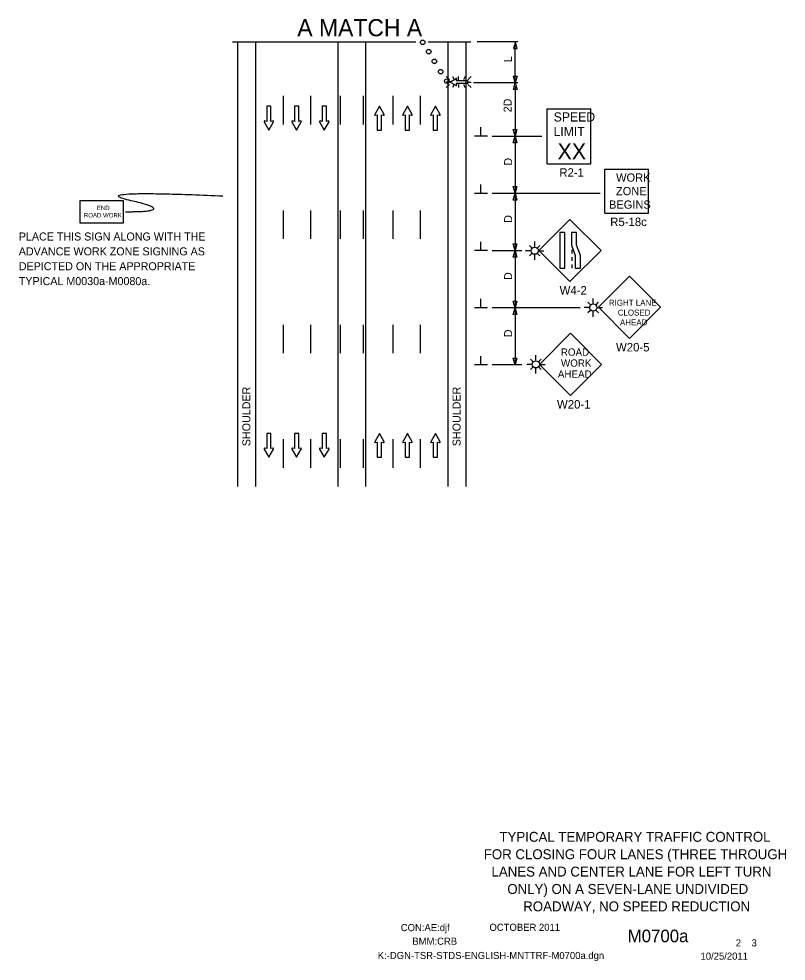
# Model space of a CAD drawing. Extents: x 16038 to 19504, y 5920 to 8321.
# Drawn here: x 17786 to 18457, y 7218 to 8042 of the extents above; entities that cross this region are included whole.
import ezdxf

# ---------------------------------------------------------------- set-up
doc = ezdxf.new("R2010")
doc.units = 0
for name, color, linetype in [('BORDER', 7, 'Continuous'), ('BORDER_SIGNAL_WO', 7, 'Continuous'), ('MT_SCRATCH_LEVEL_E', 7, 'Continuous'), ('PAVT_EDGE_EX', 7, 'Continuous'), ('TRAFFIC_SIGNS_PR', 7, 'Continuous'), ('TYPICAL_TEXT_DIMEN_PR', 7, 'Continuous')]:
    doc.layers.add(name, color=color, linetype=linetype)

msp = doc.modelspace()

# ---------------------------------------------------------------- linework, layer by layer
at = {"layer": 'BORDER'}
for p, q in [((18318.25, 7297.5), (18318.25, 7297.5)), ((18318.25, 7291.25), (18318.25, 7291.25))]:
    msp.add_line(p, q, dxfattribs=at)
at = {"layer": 'MT_SCRATCH_LEVEL_E'}
for p, q in [((18006.14, 7965.55), (18002.4, 7965.55)), ((18002.4, 7965.55), (18002.4, 7952.29)), ((18006.14, 7965.55), (18002.4, 7965.55)), ((18002.4, 7965.55), (18002.4, 7952.29)), ((18006.14, 7952.29), (18006.14, 7965.55)), ((18006.14, 7952.29), (18006.14, 7965.55)), ((18030.4, 7965.55), (18026.65, 7965.55)), ((18026.65, 7965.55), (18026.65, 7952.29)), ((18030.4, 7965.55), (18026.65, 7965.55)), ((18026.65, 7965.55), (18026.65, 7952.29)), ((18030.4, 7952.29), (18030.4, 7965.55)), ((18030.4, 7952.29), (18030.4, 7965.55)), ((18054.65, 7965.55), (18050.91, 7965.55)), ((18050.91, 7965.55), (18050.91, 7952.29)), ((18054.65, 7965.55), (18050.91, 7965.55)), ((18050.91, 7965.55), (18050.91, 7952.29)), ((18054.65, 7952.29), (18054.65, 7965.55)), ((18054.65, 7952.29), (18054.65, 7965.55)), ((18100.97, 7965.55), (18096.86, 7958.31)), ((18100.97, 7965.55), (18096.86, 7958.31)), ((18105.12, 7958.31), (18100.97, 7965.55)), ((18105.12, 7958.31), (18100.97, 7965.55)), ((18125.47, 7965.55), (18121.36, 7958.31)), ((18125.47, 7965.55), (18121.36, 7958.31)), ((18129.61, 7958.31), (18125.47, 7965.55)), ((18129.61, 7958.31), (18125.47, 7965.55)), ((18149.96, 7965.55), (18145.85, 7958.31)), ((18149.96, 7965.55), (18145.85, 7958.31)), ((18154.11, 7958.31), (18149.96, 7965.55)), ((18154.11, 7958.31), (18149.96, 7965.55)), ((18000.14, 7951.92), (18004.29, 7944.68)), ((18000.14, 7951.92), (18004.29, 7944.68)), ((18002.4, 7952.29), (18000.62, 7952.6)), ((18002.4, 7952.29), (18000.62, 7952.6)), ((18004.29, 7944.68), (18008.4, 7951.92)), ((18004.29, 7944.68), (18008.4, 7951.92)), ((18007.92, 7952.6), (18006.14, 7952.29)), ((18007.92, 7952.6), (18006.14, 7952.29)), ((18024.4, 7951.92), (18028.55, 7944.68)), ((18024.4, 7951.92), (18028.55, 7944.68)), ((18026.65, 7952.29), (18024.88, 7952.6)), ((18026.65, 7952.29), (18024.88, 7952.6)), ((18028.55, 7944.68), (18032.66, 7951.92)), ((18028.55, 7944.68), (18032.66, 7951.92)), ((18032.17, 7952.6), (18030.4, 7952.29)), ((18032.17, 7952.6), (18030.4, 7952.29)), ((18048.65, 7951.92), (18052.8, 7944.68)), ((18048.65, 7951.92), (18052.8, 7944.68)), ((18050.91, 7952.29), (18049.13, 7952.6)), ((18050.91, 7952.29), (18049.13, 7952.6)), ((18052.8, 7944.68), (18056.91, 7951.92)), ((18052.8, 7944.68), (18056.91, 7951.92)), ((18056.43, 7952.6), (18054.65, 7952.29)), ((18056.43, 7952.6), (18054.65, 7952.29)), ((18097.34, 7957.62), (18099.12, 7957.94)), ((18097.34, 7957.62), (18099.12, 7957.94)), ((18099.12, 7957.94), (18099.12, 7944.68)), ((18099.12, 7957.94), (18099.12, 7944.68)), ((18102.86, 7944.68), (18102.86, 7957.94)), ((18102.86, 7957.94), (18104.64, 7957.62)), ((18102.86, 7944.68), (18102.86, 7957.94)), ((18102.86, 7957.94), (18104.64, 7957.62)), ((18121.84, 7957.62), (18123.62, 7957.94)), ((18121.84, 7957.62), (18123.62, 7957.94)), ((18123.62, 7957.94), (18123.62, 7944.68)), ((18123.62, 7957.94), (18123.62, 7944.68)), ((18127.36, 7944.68), (18127.36, 7957.94)), ((18127.36, 7957.94), (18129.14, 7957.62)), ((18127.36, 7944.68), (18127.36, 7957.94)), ((18127.36, 7957.94), (18129.14, 7957.62)), ((18146.33, 7957.62), (18148.11, 7957.94)), ((18146.33, 7957.62), (18148.11, 7957.94)), ((18148.11, 7957.94), (18148.11, 7944.68)), ((18148.11, 7957.94), (18148.11, 7944.68)), ((18151.85, 7944.68), (18151.85, 7957.94)), ((18151.85, 7957.94), (18153.63, 7957.62)), ((18151.85, 7944.68), (18151.85, 7957.94)), ((18151.85, 7957.94), (18153.63, 7957.62)), ((18099.12, 7944.68), (18102.86, 7944.68)), ((18099.12, 7944.68), (18102.86, 7944.68)), ((18123.62, 7944.68), (18127.36, 7944.68)), ((18123.62, 7944.68), (18127.36, 7944.68)), ((18148.11, 7944.68), (18151.85, 7944.68)), ((18148.11, 7944.68), (18151.85, 7944.68)), ((18006.14, 7679.44), (18002.4, 7679.44)), ((18002.4, 7679.44), (18002.4, 7666.18)), ((18006.14, 7679.44), (18002.4, 7679.44)), ((18002.4, 7679.44), (18002.4, 7666.18)), ((18006.14, 7666.18), (18006.14, 7679.44)), ((18006.14, 7666.18), (18006.14, 7679.44)), ((18030.4, 7679.44), (18026.65, 7679.44)), ((18026.65, 7679.44), (18026.65, 7666.18)), ((18030.4, 7679.44), (18026.65, 7679.44)), ((18026.65, 7679.44), (18026.65, 7666.18)), ((18030.4, 7666.18), (18030.4, 7679.44)), ((18030.4, 7666.18), (18030.4, 7679.44)), ((18054.65, 7679.44), (18050.91, 7679.44)), ((18050.91, 7679.44), (18050.91, 7666.18)), ((18054.65, 7679.44), (18050.91, 7679.44)), ((18050.91, 7679.44), (18050.91, 7666.18)), ((18054.65, 7666.18), (18054.65, 7679.44)), ((18054.65, 7666.18), (18054.65, 7679.44)), ((18100.97, 7679.44), (18096.86, 7672.2)), ((18100.97, 7679.44), (18096.86, 7672.2)), ((18105.12, 7672.2), (18100.97, 7679.44)), ((18105.12, 7672.2), (18100.97, 7679.44)), ((18125.47, 7679.44), (18121.36, 7672.2)), ((18125.47, 7679.44), (18121.36, 7672.2)), ((18129.61, 7672.2), (18125.47, 7679.44)), ((18129.61, 7672.2), (18125.47, 7679.44)), ((18149.96, 7679.44), (18145.85, 7672.2)), ((18149.96, 7679.44), (18145.85, 7672.2)), ((18154.11, 7672.2), (18149.96, 7679.44)), ((18154.11, 7672.2), (18149.96, 7679.44)), ((18097.34, 7671.52), (18099.12, 7671.83)), ((18097.34, 7671.52), (18099.12, 7671.83)), ((18099.12, 7671.83), (18099.12, 7658.57)), ((18099.12, 7671.83), (18099.12, 7658.57)), ((18102.86, 7658.57), (18102.86, 7671.83)), ((18102.86, 7671.83), (18104.64, 7671.52)), ((18102.86, 7658.57), (18102.86, 7671.83)), ((18102.86, 7671.83), (18104.64, 7671.52)), ((18121.84, 7671.52), (18123.62, 7671.83)), ((18121.84, 7671.52), (18123.62, 7671.83)), ((18123.62, 7671.83), (18123.62, 7658.57)), ((18123.62, 7671.83), (18123.62, 7658.57)), ((18127.36, 7658.57), (18127.36, 7671.83)), ((18127.36, 7671.83), (18129.14, 7671.52)), ((18127.36, 7658.57), (18127.36, 7671.83)), ((18127.36, 7671.83), (18129.14, 7671.52)), ((18146.33, 7671.52), (18148.11, 7671.83)), ((18146.33, 7671.52), (18148.11, 7671.83)), ((18148.11, 7671.83), (18148.11, 7658.57)), ((18148.11, 7671.83), (18148.11, 7658.57)), ((18151.85, 7658.57), (18151.85, 7671.83)), ((18151.85, 7671.83), (18153.63, 7671.52)), ((18151.85, 7658.57), (18151.85, 7671.83)), ((18151.85, 7671.83), (18153.63, 7671.52)), ((18000.14, 7665.81), (18004.29, 7658.57)), ((18000.14, 7665.81), (18004.29, 7658.57)), ((18002.4, 7666.18), (18000.62, 7666.5)), ((18002.4, 7666.18), (18000.62, 7666.5)), ((18004.29, 7658.57), (18008.4, 7665.81)), ((18004.29, 7658.57), (18008.4, 7665.81)), ((18007.92, 7666.5), (18006.14, 7666.18)), ((18007.92, 7666.5), (18006.14, 7666.18)), ((18024.4, 7665.81), (18028.55, 7658.57)), ((18024.4, 7665.81), (18028.55, 7658.57)), ((18026.65, 7666.18), (18024.88, 7666.5)), ((18026.65, 7666.18), (18024.88, 7666.5)), ((18028.55, 7658.57), (18032.66, 7665.81)), ((18028.55, 7658.57), (18032.66, 7665.81)), ((18032.17, 7666.5), (18030.4, 7666.18)), ((18032.17, 7666.5), (18030.4, 7666.18)), ((18048.65, 7665.81), (18052.8, 7658.57)), ((18048.65, 7665.81), (18052.8, 7658.57)), ((18050.91, 7666.18), (18049.13, 7666.5)), ((18050.91, 7666.18), (18049.13, 7666.5)), ((18052.8, 7658.57), (18056.91, 7665.81)), ((18052.8, 7658.57), (18056.91, 7665.81)), ((18056.43, 7666.5), (18054.65, 7666.18)), ((18056.43, 7666.5), (18054.65, 7666.18)), ((18099.12, 7658.57), (18102.86, 7658.57)), ((18099.12, 7658.57), (18102.86, 7658.57)), ((18123.62, 7658.57), (18127.36, 7658.57)), ((18123.62, 7658.57), (18127.36, 7658.57)), ((18148.11, 7658.57), (18151.85, 7658.57)), ((18148.11, 7658.57), (18151.85, 7658.57))]:
    msp.add_line(p, q, dxfattribs=at)
for centre, start, end in [((18097.27, 7958.08), 150.42484, 279.96381), ((18097.27, 7958.08), 150.42484, 279.96381), ((18104.71, 7958.08), 260.03619, 29.77312), ((18104.71, 7958.08), 260.03619, 29.77312), ((18121.76, 7958.08), 150.42484, 279.96381), ((18121.76, 7958.08), 150.42484, 279.96381), ((18129.2, 7958.08), 260.03619, 29.77312), ((18129.2, 7958.08), 260.03619, 29.77312), ((18146.26, 7958.08), 150.42484, 279.96381), ((18146.26, 7958.08), 150.42484, 279.96381), ((18153.7, 7958.08), 260.03619, 29.77312), ((18153.7, 7958.08), 260.03619, 29.77312), ((18000.55, 7952.14), 80.03619, 209.77312), ((18000.55, 7952.14), 80.03619, 209.77312), ((18007.99, 7952.14), 330.42484, 99.96381), ((18007.99, 7952.14), 330.42484, 99.96381), ((18024.81, 7952.14), 80.03619, 209.77312), ((18024.81, 7952.14), 80.03619, 209.77312), ((18032.25, 7952.14), 330.42484, 99.96381), ((18032.25, 7952.14), 330.42484, 99.96381), ((18049.06, 7952.14), 80.03619, 209.77312), ((18049.06, 7952.14), 80.03619, 209.77312), ((18056.5, 7952.14), 330.42484, 99.96381), ((18056.5, 7952.14), 330.42484, 99.96381), ((18097.27, 7671.97), 150.42484, 279.96381), ((18097.27, 7671.97), 150.42484, 279.96381), ((18104.71, 7671.98), 260.03619, 29.77312), ((18104.71, 7671.98), 260.03619, 29.77312), ((18121.76, 7671.97), 150.42484, 279.96381), ((18121.76, 7671.97), 150.42484, 279.96381), ((18129.2, 7671.98), 260.03619, 29.77312), ((18129.2, 7671.98), 260.03619, 29.77312), ((18146.26, 7671.97), 150.42484, 279.96381), ((18146.26, 7671.97), 150.42484, 279.96381), ((18153.7, 7671.98), 260.03619, 29.77312), ((18153.7, 7671.98), 260.03619, 29.77312), ((18000.55, 7666.04), 80.03619, 209.77312), ((18000.55, 7666.04), 80.03619, 209.77312), ((18007.99, 7666.04), 330.42484, 99.96381), ((18007.99, 7666.04), 330.42484, 99.96381), ((18024.81, 7666.04), 80.03619, 209.77312), ((18024.81, 7666.04), 80.03619, 209.77312), ((18032.25, 7666.04), 330.42484, 99.96381), ((18032.25, 7666.04), 330.42484, 99.96381), ((18049.06, 7666.04), 80.03619, 209.77312), ((18049.06, 7666.04), 80.03619, 209.77312), ((18056.5, 7666.04), 330.42484, 99.96381), ((18056.5, 7666.04), 330.42484, 99.96381)]:
    msp.add_arc(centre, 0.463, start, end, dxfattribs=at)
at = {"layer": 'PAVT_EDGE_EX'}
for p, q in [((17976.73, 8021.87), (17976.73, 7633.14)), ((17992.73, 8021.87), (17992.73, 7633.14)), ((18064.73, 8021.87), (18064.73, 7633.14)), ((18088.73, 8021.87), (18088.73, 7633.14)), ((18160.73, 8021.87), (18160.73, 7633.14)), ((18176.73, 8021.87), (18176.73, 7633.14))]:
    msp.add_line(p, q, dxfattribs=at)
at = {"layer": 'TRAFFIC_SIGNS_PR'}
for p, q in [((18159.43, 7991.52), (18162.25, 7988.7)), ((18164.86, 7991.52), (18166.07, 7989.43)), ((18170.33, 7988.7), (18170.33, 7991.52)), ((18176.12, 7991.52), (18174.49, 7988.7)), ((18178.42, 7988.7), (18181.24, 7991.52)), ((18162.25, 7986.67), (18159.43, 7986.67)), ((18159.43, 7981.82), (18162.25, 7984.64)), ((18166.15, 7984), (18164.89, 7981.82)), ((18170.33, 7984.64), (18170.33, 7981.82)), ((18174.47, 7984.64), (18176.1, 7981.82)), ((18178.42, 7986.67), (18181.24, 7986.67)), ((18178.42, 7984.64), (18181.24, 7981.82)), ((18247.7, 7963.28), (18286.1, 7963.28)), ((18247.7, 7915.28), (18247.7, 7963.28)), ((18286.1, 7915.28), (18286.1, 7963.28)), ((18247.7, 7915.28), (18286.1, 7915.28)), ((18298.11, 7872.16), (18298.11, 7910.56)), ((18298.11, 7910.56), (18336.51, 7910.56)), ((18336.51, 7872.16), (18336.51, 7910.56)), ((18298.11, 7872.16), (18336.51, 7872.16)), ((18267.74, 7866.59), (18240.58, 7839.43)), ((18294.89, 7839.43), (18267.74, 7866.59)), ((18234.34, 7841.73), (18232.24, 7843.84)), ((18236.85, 7842.77), (18236.85, 7847.27)), ((18239.36, 7841.73), (18241.47, 7843.84)), ((18233.7, 7839.22), (18228.87, 7839.22)), ((18234.34, 7836.71), (18232.24, 7834.61)), ((18236.85, 7831.27), (18236.85, 7835.67)), ((18239.36, 7836.71), (18241.46, 7834.61)), ((18240, 7839.22), (18244.88, 7839.22)), ((18240.58, 7839.43), (18267.74, 7812.28)), ((18267.74, 7812.28), (18294.89, 7839.43)), ((18269.38, 7839.92), (18269.38, 7836.72)), ((18269.38, 7833.52), (18269.38, 7830.32)), ((18269.38, 7827.12), (18269.38, 7823.92)), ((18319.82, 7816.87), (18292.66, 7789.71)), ((18346.97, 7789.71), (18319.82, 7816.87)), ((18285.59, 7792.01), (18283.48, 7794.11)), ((18288.1, 7793.05), (18288.1, 7797.55)), ((18290.61, 7792.01), (18292.72, 7794.11)), ((18284.94, 7789.49), (18280.11, 7789.49)), ((18285.58, 7786.98), (18283.48, 7784.87)), ((18288.1, 7781.53), (18288.1, 7785.94)), ((18290.61, 7786.98), (18292.72, 7784.87)), ((18291.25, 7789.49), (18296.13, 7789.49)), ((18292.66, 7789.71), (18319.82, 7762.56)), ((18319.82, 7762.56), (18346.97, 7789.71)), ((18268.2, 7767.01), (18241.02, 7739.82)), ((18295.39, 7739.82), (18268.2, 7767.01)), ((18235.35, 7742.34), (18233.24, 7744.45)), ((18237.86, 7743.38), (18237.86, 7747.88)), ((18240.38, 7742.34), (18242.49, 7744.45)), ((18234.71, 7739.82), (18229.87, 7739.82)), ((18235.35, 7737.31), (18233.24, 7735.2)), ((18237.86, 7731.86), (18237.86, 7736.27)), ((18240.38, 7737.31), (18242.48, 7735.2)), ((18241.02, 7739.82), (18245.9, 7739.82)), ((18241.02, 7739.82), (18268.2, 7712.64)), ((18268.2, 7712.64), (18295.39, 7739.82))]:
    msp.add_line(p, q, dxfattribs=at)
for points in [[(18168.01, 7983.65), (18162.7, 7986.67), (18168.01, 7989.71)], [(18168.51, 7989.35), (18168.28, 7988.05), (18178, 7988.05), (18178, 7985.31), (18168.28, 7985.31), (18168.51, 7984.01)]]:
    msp.add_lwpolyline(points, dxfattribs=at)
for points in [[(17838.87, 7863.56), (17877.26, 7863.56), (17877.26, 7882.76), (17838.87, 7882.76)], [(18258.84, 7855.17), (18258.84, 7823.92), (18263.33, 7823.92), (18263.33, 7855.17)], [(18268.98, 7855.17), (18268.98, 7843.99), (18272.32, 7835.11), (18272.32, 7823.92), (18276.82, 7823.92), (18276.82, 7835.11), (18273.47, 7843.99), (18273.47, 7855.17)]]:
    msp.add_lwpolyline(points, close=True, dxfattribs=at)
for centre, radius in [((18138.91, 8021.37), 2), ((18144.15, 8013.2), 2), ((18149.13, 8004.78), 2), ((18154.63, 7995.74), 2), ((18159.96, 7987.38), 2), ((18236.85, 7839.22), 3.15), ((18288.1, 7789.49), 3.15), ((18237.86, 7739.83), 3.15)]:
    msp.add_circle(centre, radius, dxfattribs=at)
for centre, start, end in [((18168.17, 7989.41), 350.04067, 118.51671), ((18168.17, 7983.95), 241.10835, 9.26922)]:
    msp.add_arc(centre, 0.341, start, end, dxfattribs=at)
msp.add_open_spline([(17878.81, 7873.28), (17926.05, 7873.28), (17841.02, 7892.62), (17964.12, 7887.13)], degree=2, dxfattribs=at)
at = {"layer": 'TYPICAL_TEXT_DIMEN_PR'}
for p, q in [((17972.43, 8021.87), (18132.84, 8021.87)), ((18064.73, 8021.87), (18088.73, 8021.87)), ((18143.74, 8021.87), (18181.03, 8021.87)), ((18222.05, 8021.88), (18186.49, 8021.87)), ((18219.96, 8021.9), (18218.39, 8016.04)), ((18218.39, 8016.04), (18219.96, 8016.04)), ((18219.9, 7985.9), (18219.9, 8020.72)), ((18221.53, 8016.04), (18219.96, 8021.9)), ((18219.96, 8016.04), (18221.53, 8016.04)), ((18219.9, 7986.05), (18218.33, 7991.91)), ((18218.33, 7991.91), (18219.9, 7991.91)), ((18219.9, 7991.91), (18221.47, 7991.91)), ((18221.47, 7991.91), (18219.9, 7986.05)), ((18222.06, 7986.03), (18183.22, 7986.03)), ((18218.32, 7980.21), (18219.89, 7986.07)), ((18219.81, 7982.84), (18219.81, 7940.02)), ((18219.89, 7986.07), (18221.46, 7980.21)), ((18219.89, 7980.21), (18218.32, 7980.21)), ((18221.46, 7980.21), (18219.89, 7980.21)), ((18189.85, 7939.31), (18189.85, 7947.09)), ((18219.67, 7939.36), (18218.1, 7945.22)), ((18218.1, 7945.22), (18219.67, 7945.22)), ((18219.67, 7945.22), (18221.24, 7945.22)), ((18221.24, 7945.22), (18219.67, 7939.36)), ((18195.48, 7939.31), (18184.23, 7939.31)), ((18199.73, 7939.31), (18243.13, 7939.31)), ((18199.73, 7939.31), (18225.73, 7939.31)), ((18218.1, 7933.5), (18219.67, 7939.36)), ((18219.67, 7933.5), (18218.1, 7933.5)), ((18219.67, 7939.36), (18221.24, 7933.5)), ((18219.67, 7939.36), (18219.67, 7889.36)), ((18221.24, 7933.5), (18219.67, 7933.5)), ((18189.85, 7889.31), (18189.85, 7897.09)), ((18219.67, 7889.36), (18218.1, 7895.22)), ((18218.1, 7895.22), (18219.67, 7895.22)), ((18219.67, 7895.22), (18221.24, 7895.22)), ((18221.24, 7895.22), (18219.67, 7889.36)), ((18195.48, 7889.31), (18184.23, 7889.31)), ((18294.1, 7889.31), (18199.73, 7889.31)), ((18218.1, 7883.5), (18219.67, 7889.36)), ((18219.67, 7889.36), (18221.24, 7883.5)), ((18219.67, 7889.36), (18219.67, 7839.36)), ((18219.67, 7883.5), (18218.1, 7883.5)), ((18221.24, 7883.5), (18219.67, 7883.5)), ((18189.85, 7839.31), (18189.85, 7847.09)), ((18219.67, 7839.36), (18218.1, 7845.22)), ((18218.1, 7845.22), (18219.67, 7845.22)), ((18219.67, 7845.22), (18221.24, 7845.22)), ((18221.24, 7845.22), (18219.67, 7839.36)), ((18195.48, 7839.31), (18184.23, 7839.31)), ((18199.73, 7839.31), (18225.73, 7839.31)), ((18199.73, 7839.31), (18225.73, 7839.31)), ((18218.1, 7833.5), (18219.67, 7839.36)), ((18219.67, 7839.36), (18221.24, 7833.5)), ((18219.67, 7839.36), (18219.67, 7789.36)), ((18219.67, 7833.5), (18218.1, 7833.5)), ((18221.24, 7833.5), (18219.67, 7833.5)), ((18189.85, 7789.31), (18189.85, 7797.09)), ((18219.67, 7789.36), (18218.1, 7795.22)), ((18218.1, 7795.22), (18219.67, 7795.22)), ((18219.67, 7795.22), (18221.24, 7795.22)), ((18221.24, 7795.22), (18219.67, 7789.36)), ((18195.48, 7789.31), (18184.23, 7789.31)), ((18276.53, 7789.31), (18199.73, 7789.31)), ((18218.1, 7783.5), (18219.67, 7789.36)), ((18219.67, 7789.36), (18221.24, 7783.5)), ((18219.67, 7789.36), (18219.67, 7739.36)), ((18219.67, 7783.5), (18218.1, 7783.5)), ((18221.24, 7783.5), (18219.67, 7783.5)), ((18189.85, 7739.31), (18189.85, 7747.09)), ((18219.67, 7739.36), (18218.1, 7745.22)), ((18218.1, 7745.22), (18219.67, 7745.22)), ((18219.67, 7745.22), (18221.24, 7745.22)), ((18221.24, 7745.22), (18219.67, 7739.36)), ((18195.48, 7739.31), (18184.23, 7739.31)), ((18225.73, 7739.31), (18199.73, 7739.31))]:
    msp.add_line(p, q, dxfattribs=at)
for points in [[(18016.73, 7974.49), (18016.73, 7949.49)], [(18040.73, 7974.49), (18040.73, 7949.49)], [(18066.73, 7974.49), (18066.73, 7949.49)], [(18086.73, 7974.49), (18086.73, 7949.49)], [(18112.73, 7974.49), (18112.73, 7949.49)], [(18136.73, 7974.49), (18136.73, 7949.49)], [(18016.73, 7874.49), (18016.73, 7849.49)], [(18040.73, 7874.49), (18040.73, 7849.49)], [(18066.73, 7874.49), (18066.73, 7849.49)], [(18086.73, 7874.49), (18086.73, 7849.49)], [(18112.73, 7874.49), (18112.73, 7849.49)], [(18136.73, 7874.49), (18136.73, 7849.49)], [(18016.73, 7774.49), (18016.73, 7749.49)], [(18040.73, 7774.49), (18040.73, 7749.49)], [(18066.73, 7774.49), (18066.73, 7749.49)], [(18086.73, 7774.49), (18086.73, 7749.49)], [(18112.73, 7774.49), (18112.73, 7749.49)], [(18136.73, 7774.49), (18136.73, 7749.49)], [(18016.73, 7674.49), (18016.73, 7649.49)], [(18040.73, 7674.49), (18040.73, 7649.49)], [(18066.73, 7674.49), (18066.73, 7649.49)], [(18086.73, 7674.49), (18086.73, 7649.49)], [(18112.73, 7674.49), (18112.73, 7649.49)], [(18136.73, 7674.49), (18136.73, 7649.49)]]:
    msp.add_lwpolyline(points, dxfattribs=at)

# ---------------------------------------------------------------- texts
at = {"layer": 'BORDER'}
for s, p in [('TYPICAL TEMPORARY TRAFFIC CONTROL', (18206.02, 7322.45)), ('FOR CLOSING FOUR LANES (THREE THROUGH', (18192.29, 7307.25)), ('LANES AND CENTER LANE FOR LEFT TURN', (18199.07, 7292.05)), ('ONLY) ON A SEVEN-LANE UNDIVIDED', (18212.91, 7276.85)), ('ROADWAY, NO SPEED REDUCTION', (18226.83, 7261.64))]:
    msp.add_text(s, height=8.6739, dxfattribs=at).set_placement(p)
at = {"layer": 'BORDER_SIGNAL_WO'}
for s, height, p in [('CON:AE:djf', 6.2, (18119.69, 7244.31)), ('    OCTOBER 2011    ', 6.2, (18188.08, 7244.59)), ('    M0700a   ', 11, (18301.86, 7234.63)), ('BMM:CRB   ', 6.2, (18129.81, 7232.42)), (' 2    3 ', 6.2, (18410.45, 7230.95)), ('K:-DGN-TSR-STDS-ENGLISH-MNTTRF-M0700a.dgn        ', 6.2, (18099.55, 7219.96)), ('10/25/2011    ', 6.2, (18381.93, 7219.38))]:
    msp.add_text(s, height=height, dxfattribs=at).set_placement(p)
at = {"layer": 'TRAFFIC_SIGNS_PR'}
for s, height, p in [('SPEED', 8, (18253.47, 7952.15)), ('LIMIT', 8, (18253.31, 7939.35)), ('XX', 14.031, (18256.81, 7919.04)), ('R2-1', 7.44, (18258.38, 7903.85)), ('WORK', 7.217, (18308.11, 7899.53)), ('ZONE', 7.217, (18307.99, 7887.72)), ('END', 3.831, (17853.87, 7874.69)), ('BEGINS', 7.217, (18301.92, 7875.91)), ('ROAD WORK', 3.831, (17842.47, 7868.31)), ('R5-18c', 7.44, (18302.92, 7860.72)), ('PLACE THIS SIGN ALONG WITH THE', 7, (17785.54, 7848.12)), ('ADVANCE WORK ZONE SIGNING AS', 7, (17785.54, 7835.12)), ('DEPICTED ON THE APPROPRIATE', 7, (17785.54, 7822.12)), ('TYPICAL M0030a-M0080a.', 7, (17785.54, 7809.12)), ('W4-2', 7.44, (18258.7, 7800.84)), ('RIGHT LANE', 5.2, (18301.74, 7791.11)), ('CLOSED', 5.2, (18309.53, 7782.51)), ('AHEAD', 5.2, (18311.47, 7773.91)), ('ROAD', 6.408, (18259.74, 7747.37)), ('W20-5', 7.44, (18307.99, 7751.12)), ('WORK', 6.408, (18259.84, 7737.76)), ('AHEAD', 6.408, (18257.15, 7728.15)), ('W20-1', 7.449, (18256.36, 7701.19))]:
    msp.add_text(s, height=height, dxfattribs=at).set_placement(p)
at = {"layer": 'TYPICAL_TEXT_DIMEN_PR'}
msp.add_text('A MATCH A', height=15, dxfattribs=at).set_placement((18029.17, 8026.68))
for s, p in [('L', (18217.03, 8003.87)), ('2D', (18216.66, 7960.18)), ('D', (18217.12, 7913.58)), ('D', (18217.12, 7863.58)), ('D', (18217.12, 7813.58)), ('D', (18217.12, 7763.58)), ('SHOULDER', (17988.1, 7668.3)), ('SHOULDER', (18172.01, 7668.3))]:
    msp.add_text(s, height=7, rotation=90, dxfattribs=at).set_placement(p)

doc.saveas('drawing.dxf')
